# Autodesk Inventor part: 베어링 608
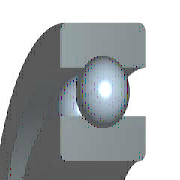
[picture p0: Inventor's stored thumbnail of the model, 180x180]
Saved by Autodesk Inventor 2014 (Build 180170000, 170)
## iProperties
IsCustomPart: 1
Created: 2012-02
Part Number: 베어링 608
Material: 강철, 연강
Description: 깊은 그루브 볼 베어링
Document SubType Name: Modeling
Standard: KS B 2023
Designer: mduedu
Standards Organization: KS
Language: ko-KR
Size Designation: 608 - 8 x 22 x 7
Categories: <MemberInstance><Categories><Category DisplayName="샤프트 부품" InternalName="7f7aeb1f-a693-4053-b835-cee3144e0d98" Mnemonic="SHFT"><Category DisplayName="베어링" Inter
Density: 7.86 g/cm^3
Appearance: Yellow
Mass: 10.9696 g
Surface Area: 20.0754 cm^2
Volume: 1.39562 cm^3
Author: mduedu
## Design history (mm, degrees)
sketch "스케치" dims "d0" = 3.64 (= -0.26 x WD + 0.26 x BD)
  geometry: L1 (1.68, 7.5)-(5.32, 7.5); L2 (3.5, 7.5)-(3.5, 5.68); L3 (3.5, 7.5)-(3.5, 9.32); L4 (2.148, 6.282)-(0, 6.282); L5 (0, 4)-(7, 4); L6 (2.148, 8.718)-(0, 8.718); L7 (0, 11)-(7, 11); L8 (7, 4)-(7, 6.282); L9 (4.852, 6.282)-(7, 6.282); L10 (4.852, 8.718)-(7, 8.718); L11 (7, 11)-(7, 8.718); L12 (-1.4, 0)-(8.4, 0) reference; L13 (0, -0.3)-(0, 5.3) reference
  constraints: 22 end point, 4 point on line, 2 collinear, 2 perpendicular, 2 symmetric about line, 1 midpoint, 1 parallel, 14 other
  dimensions: "d9" = 8 diameter of L5 L12 (= WD); "d11" = 22 diameter of L7 L12 (= BD); "d12" = 7 distance between parallel lines of L8 L13 (= KB); "d13" = 12.564 diameter of L9 L12 (= 0.326 x BD + 0.674 x WD)
revolve "본체" stored, may be unused: angle "d6" = 90 deg
revolve "볼" stored, may be unused: angle "d7" = 90 deg
pattern_circular "IDS_ARRAYBALL[SIMPL:T]" dims angle "d3" = 360 deg
body "Solid1"
fillet "모깎기1" dims "d1" = 0.3 (= KRS)
other parameters: "WD" = 8 [user parameter; used in 5 equation terms], "BD" = 22 [user parameter; used in 5 equation terms], "KB" = 7 [user parameter; used in 1 equation term], "KRS" = 0.3 [user parameter; used in 1 equation term], "d4" = 0, "d5" = 0, "d8" = 0, "d14" = 0, "d15" = 0, "BBA" = 0 [user parameter], "BC0" = 1370000 [user parameter], "BC" = 3250000 [user parameter], "BR" = 11 (= 0.5 x BD) [user parameter], "WR" = 4 (= 0.5 x WD) [user parameter]
